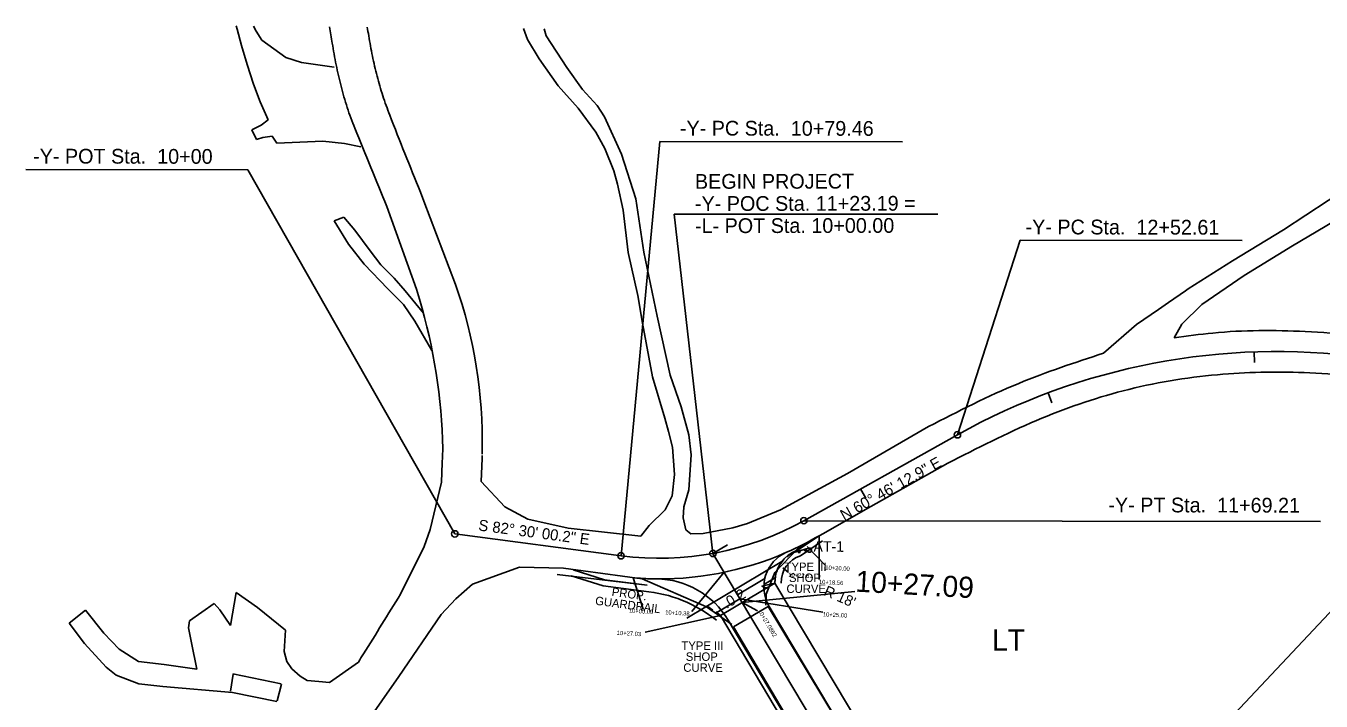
# Model space of a CAD drawing. Extents: x 757145 to 758829, y 592169 to 594973.
# Drawn here: x 757323 to 757937, y 594652 to 594973 of the extents above; entities that cross this region are included whole.
import ezdxf

# ---------------------------------------------------------------- set-up
doc = ezdxf.new("R2010")
doc.units = 0
for name, color, linetype in [('COGO Default Point Elevation', 7, 'Continuous'), ('Default', 7, 'Continuous'), ('Exist Horizontal Alignment', 7, 'Continuous'), ('Exist Horizontal Alignment Direction Label', 7, 'Continuous'), ('Exist Horizontal Alignment Station Label', 7, 'Continuous'), ('Exist Horizontal Alignment Tick Small', 7, 'Continuous'), ('Prop Dimension', 7, 'Continuous'), ('Prop EOT', 7, 'Continuous'), ('Prop Guardrail Anchor Unit CELL', 7, 'Continuous'), ('Prop Guardrail Shop Curved', 7, 'Continuous'), ('Prop Horizontal Alignment Direction Label', 7, 'Continuous'), ('Prop Horizontal Alignment Tick Small', 7, 'Continuous'), ('Prop Paved Shoulder', 7, 'Continuous'), ('Prop Rem of Exist Asph Pvmt', 7, 'Continuous'), ('Prop Roadway Bridge', 7, 'Continuous'), ('Prop Structure Anchor Unit CELL', 7, 'Continuous'), ('Prop Superelevation  Arrow CELL', 7, 'Continuous'), ('Scratch_Level_4', 7, 'Continuous')]:
    doc.layers.add(name, color=color, linetype=linetype)

msp = doc.modelspace()

# ---------------------------------------------------------------- linework, layer by layer
at = {"layer": 'COGO Default Point Elevation'}
for p, q in [((757689.05, 594723.55), (757692.46, 594724.51)), ((757689.05, 594723.55), (757689.73, 594723.74)), ((757689.27, 594722.78), (757689.05, 594723.55)), ((757689.05, 594723.55), (757689.94, 594722.96)), ((757689.73, 594723.74), (757689.27, 594722.78)), ((757689.94, 594722.96), (757689.27, 594722.78)), ((757689.73, 594723.74), (757689.94, 594722.96)), ((757691.98, 594724.37), (757692.65, 594724.56)), ((757692.2, 594723.6), (757691.98, 594724.37)), ((757691.98, 594724.37), (757692.87, 594723.79)), ((757692.65, 594724.56), (757692.2, 594723.6)), ((757692.87, 594723.79), (757692.2, 594723.6)), ((757692.53, 594724.53), (757692.4, 594724.49)), ((757692.53, 594724.53), (757692.4, 594724.49)), ((757692.46, 594724.51), (757694.12, 594724.97)), ((757692.65, 594724.56), (757692.75, 594724.22)), ((757692.65, 594724.56), (757692.75, 594724.22)), ((757692.65, 594724.56), (757692.87, 594723.79)), ((757693.78, 594723.23), (757692.82, 594723.97)), ((757681.31, 594718.64), (757636.34, 594691.82)), ((757660.32, 594702.85), (757673.24, 594710.55)), ((757672.8, 594707.74), (757678.13, 594710.92)), ((757650.45, 594694.41), (757661.44, 594700.97))]:
    msp.add_line(p, q, dxfattribs=at)
for points in [[(757698.92, 594710.07), (757698.96, 594730.84)], [(757701.95, 594716.8), (757693.23, 594725.75)], [(757615.51, 594695.98), (757610.85, 594710.9)], [(757638.68, 594694.86), (757653.95, 594713.53)], [(757684.37, 594713.38), (757681.75, 594715.63)], [(757700.78, 594694.56), (757661.44, 594700.97)], [(757669.81, 594695.16), (757662.51, 594699.18)], [(757616.45, 594685.11), (757652.18, 594693.08)]]:
    msp.add_lwpolyline(points, dxfattribs=at)
msp.add_lwpolyline([(757678.01, 594708.32), (757671.83, 594707), (757674.03, 594705.97)], close=True, dxfattribs=at)
msp.add_ellipse((757694.39, 594724.02), major_axis=(-0.268, 0.956), ratio=0.995379, start_param=2.210226, end_param=6.283185, dxfattribs=at)
at = {"layer": 'Default'}
for p, q in [((757423.26, 594970.9), (757422.7, 594972.52)), ((757425.18, 594963.15), (757423.26, 594970.9)), ((757430.89, 594972.44), (757432.26, 594970.02)), ((757432.26, 594970.02), (757434.96, 594965.68)), ((757558.81, 594971.28), (757560.74, 594966.05)), ((757568.63, 594971.19), (757569.64, 594967.81)), ((757427.93, 594954.21), (757425.18, 594963.15)), ((757434.96, 594965.68), (757446.28, 594957.48)), ((757560.74, 594966.05), (757566.33, 594956.95)), ((757569.64, 594967.81), (757579.41, 594952.72)), ((757446.28, 594957.48), (757453.72, 594955.16)), ((757566.33, 594956.95), (757575.26, 594944.1)), ((757430.93, 594944.82), (757427.93, 594954.21)), ((757453.72, 594955.16), (757469.17, 594952.98)), ((757579.41, 594952.72), (757586.89, 594942.33)), ((757434.12, 594936.47), (757430.93, 594944.82)), ((757575.26, 594944.1), (757584.82, 594933.45)), ((757586.89, 594942.33), (757593.71, 594934.86)), ((757437.85, 594928.03), (757434.12, 594936.47)), ((757584.82, 594933.45), (757593.16, 594922.16)), ((757597.32, 594929.47), (757593.71, 594934.86)), ((757430.17, 594923.29), (757434.51, 594925.52)), ((757434.51, 594925.52), (757437.85, 594928.03)), ((757597.32, 594929.47), (757605.37, 594911.77)), ((757432.29, 594918.66), (757430.17, 594923.29)), ((757435.38, 594919.64), (757432.31, 594918.66)), ((757439.81, 594920.25), (757435.38, 594919.64)), ((757441.96, 594917), (757439.81, 594920.25)), ((757593.16, 594922.16), (757597.48, 594914.35)), ((757432.31, 594918.66), (757432.29, 594918.66)), ((757463.75, 594917.95), (757441.96, 594917)), ((757474, 594916.83), (757463.75, 594917.95)), ((757481.86, 594915.17), (757474, 594916.83)), ((757597.48, 594914.35), (757601.7, 594903.82)), ((757605.37, 594911.77), (757612.13, 594890.5)), ((757601.7, 594903.82), (757603.45, 594897.45)), ((757603.45, 594897.45), (757606.15, 594885.14)), ((757918.98, 594875.82), (757952.2, 594897.78)), ((757511.72, 594889.44), (757510.06, 594893.76)), ((757526.63, 594849.91), (757511.72, 594889.44)), ((757612.13, 594890.5), (757615.84, 594865.29)), ((757923.25, 594868.26), (757966.66, 594893.94)), ((757494.16, 594886.93), (757508.12, 594847.7)), ((757606.15, 594885.14), (757608.52, 594865.11)), ((757469.15, 594880.12), (757473.67, 594881.91)), ((757476.01, 594869.03), (757469.15, 594880.12)), ((757473.67, 594881.91), (757479.01, 594875.74)), ((757479.01, 594875.74), (757486.25, 594865.85)), ((757894.9, 594861.12), (757918.98, 594875.82)), ((757483.38, 594859.6), (757476.01, 594869.03)), ((757486.25, 594865.85), (757491.31, 594859.28)), ((757608.52, 594865.11), (757613.02, 594844.75)), ((757615.84, 594865.29), (757622.27, 594834.96)), ((757900.31, 594854.25), (757923.25, 594868.26)), ((757494.57, 594847.94), (757483.38, 594859.6)), ((757491.31, 594859.28), (757497.67, 594852.98)), ((757873.88, 594847.82), (757894.9, 594861.12)), ((757497.67, 594852.98), (757502.79, 594846.94)), ((757880.33, 594840.47), (757900.31, 594854.25)), ((757501.95, 594840.38), (757494.57, 594847.94)), ((757502.79, 594846.94), (757511.52, 594836.4)), ((757508.12, 594847.7), (757509.56, 594842.92)), ((757864.58, 594841.45), (757872.59, 594846.95)), ((757872.59, 594846.95), (757873.88, 594847.82)), ((757507.44, 594832.58), (757501.95, 594840.38)), ((757613.02, 594844.75), (757615.2, 594831.59)), ((757859.72, 594838.05), (757864.58, 594841.45)), ((757870.8, 594831.08), (757880.33, 594840.47)), ((757628.42, 594806.97), (757622.27, 594834.96)), ((757849.4, 594830.99), (757859.72, 594838.05)), ((757515.51, 594818.65), (757507.44, 594832.58)), ((757615.2, 594831.59), (757619.97, 594806.13)), ((757833.68, 594817.38), (757849.4, 594830.99)), ((757867.17, 594824.62), (757870.8, 594831.08)), ((757619.97, 594806.13), (757625.78, 594786.52)), ((757633.59, 594791.87), (757628.42, 594806.97)), ((757633.59, 594791.87), (757637.19, 594778.68)), ((757625.78, 594786.52), (757627.64, 594780.23)), ((757629.54, 594772.83), (757627.64, 594780.23)), ((757637.19, 594778.68), (757638.26, 594769.12)), ((757750.76, 594782.54), (757712.4, 594760.37)), ((757520.59, 594772.11), (757520.36, 594765.05)), ((757630.39, 594759.79), (757629.54, 594772.83)), ((757519.95, 594756.28), (757520.33, 594765.47)), ((757539.35, 594767.49), (757538.84, 594756.62)), ((757539.25, 594769.5), (757539.22, 594771.23)), ((757539.29, 594768.81), (757539.35, 594767.49)), ((757638.26, 594769.12), (757637.2, 594752.56)), ((757629.3, 594749.68), (757630.39, 594759.79)), ((757712.4, 594760.37), (757680.65, 594743.18)), ((757723.49, 594744.76), (757759.9, 594765.22)), ((757538.84, 594756.62), (757550.07, 594744.6)), ((757626.02, 594743.1), (757629.3, 594749.68)), ((757637.2, 594752.56), (757634.83, 594744.49)), ((757550.07, 594744.6), (757560.92, 594738.65)), ((757618.42, 594735.63), (757626.02, 594743.1)), ((757634.83, 594744.49), (757634.5, 594739.33)), ((757680.65, 594743.18), (757665.08, 594736.68)), ((757560.92, 594738.65), (757580.09, 594734.41)), ((757614.51, 594730.61), (757618.42, 594735.63)), ((757634.5, 594739.33), (757635.82, 594733.69)), ((757658, 594734.6), (757665.08, 594736.68)), ((757580.09, 594734.41), (757614.51, 594730.61)), ((757635.82, 594733.69), (757638.23, 594731.77)), ((757638.23, 594731.77), (757643.98, 594731.82)), ((757643.98, 594731.82), (757658, 594734.6)), ((757534.78, 594707.93), (757526.78, 594700.88)), ((757400.58, 594690.5), (757412.35, 594698.79)), ((757412.35, 594698.79), (757414.95, 594695.65)), ((757420.03, 594688.24), (757422.77, 594703.93)), ((757422.77, 594703.93), (757432.85, 594696.85)), ((757526.78, 594700.88), (757519.93, 594693.54)), ((757343.61, 594689.37), (757351.37, 594695.52)), ((757351.37, 594695.52), (757359.96, 594684.61)), ((757414.95, 594695.65), (757420.03, 594688.24)), ((757432.85, 594696.85), (757446.1, 594686.14)), ((757658.35, 594687.7), (757674.88, 594697.27)), ((757674.88, 594697.27), (757706.73, 594644.4)), ((757350.87, 594679.82), (757343.61, 594689.37)), ((757400.06, 594687.14), (757400.58, 594690.5)), ((757401.5, 594680.14), (757400.06, 594687.14)), ((757446.1, 594686.14), (757445.53, 594676.02)), ((757700.05, 594617.37), (757658.35, 594687.7)), ((757361.09, 594668.6), (757350.87, 594679.82)), ((757359.96, 594684.61), (757367.33, 594677.09)), ((757404.15, 594667.6), (757401.5, 594680.14)), ((757367.33, 594677.09), (757376.5, 594671.26)), ((757445.53, 594676.02), (757446.75, 594671.15)), ((757365.9, 594664.69), (757361.09, 594668.6)), ((757376.5, 594671.26), (757388.53, 594669.82)), ((757388.53, 594669.82), (757404.15, 594667.6)), ((757446.75, 594671.15), (757449.17, 594667.76)), ((757449.17, 594667.76), (757453, 594664.26)), ((757466.98, 594661.19), (757480.66, 594670.98)), ((757376.61, 594660.69), (757365.9, 594664.69)), ((757421.36, 594665.18), (757420.04, 594657.09)), ((757444.04, 594660.67), (757421.1, 594665.45)), ((757453, 594664.26), (757456.44, 594662.25)), ((757456.44, 594662.25), (757461.89, 594661.73)), ((757461.89, 594661.73), (757466.98, 594661.19)), ((757387.91, 594659.34), (757376.61, 594660.69)), ((757421.04, 594656.49), (757387.91, 594659.34)), ((757442.04, 594652.32), (757421.04, 594656.49)), ((757442.19, 594652.58), (757444.17, 594660.54))]:
    msp.add_line(p, q, dxfattribs=at)
for points in [[(757500.54, 594703.08), (757511.83, 594725.74), (757514.69, 594733.79), (757519.95, 594756.28)], [(757519.93, 594693.54), (757499.75, 594664.06), (757475.67, 594629.54), (757450.9, 594594.8)]]:
    msp.add_lwpolyline(points, dxfattribs=at)
for centre, major_axis, ratio, start_param, end_param in [((757319.23, 594776.33), (15.83, 219.6), 0.999445, 4.761154, 5.12504), ((757264.11, 594768.46), (-41.51, 256.49), 0.986972, 4.56805, 4.844759)]:
    msp.add_ellipse(centre, major_axis=major_axis, ratio=ratio, start_param=start_param, end_param=end_param, dxfattribs=at)
for points in [[(757467.01, 594972.12), (757468.24, 594964.36), (757469.11, 594959.21), (757470.09, 594954.07), (757472.42, 594943.87), (757475.34, 594933.83), (757477.04, 594928.9), (757478.93, 594924.04), (757494.16, 594886.93)], [(757510.06, 594893.76), (757495.51, 594930.24), (757492.22, 594939.39), (757489.5, 594948.74), (757487.29, 594958.24), (757486.36, 594963.02), (757485.53, 594967.81), (757484.86, 594971.95)], [(758438.83, 594691.7), (758388.12, 594713.96), (758348.23, 594729.88), (758301, 594745.68), (758262.18, 594757.5), (758218.1, 594769.85), (758179.06, 594780.3), (758137.21, 594790.72), (758099.24, 594799.92), (758057.04, 594808.54), (758015.02, 594816.54), (757976.3, 594823.06), (757929.26, 594827.65), (757885.54, 594826.92), (757867.17, 594824.62)], [(757833.68, 594817.38), (757793.57, 594803.08), (757750.76, 594782.54)], [(757759.9, 594765.22), (757801.95, 594785.45), (757843.04, 594799.54), (757887.75, 594807.17), (757928.75, 594808.19), (757973.34, 594803.82), (758011.28, 594797.5), (758054.09, 594789.21), (758096.75, 594780.39), (758132.99, 594771.58), (758175.84, 594760.81), (758214.12, 594750.43), (758258.48, 594738.29), (758295.65, 594726.54), (758342.77, 594710.33), (758380.69, 594695.36), (758421.02, 594677.79), (758431.33, 594673.19)], [(757480.66, 594670.98), (757483.04, 594674.79), (757500.54, 594703.08)]]:
    msp.add_spline(points, degree=3, dxfattribs=at)
at = {"layer": 'Exist Horizontal Alignment'}
for p, q in [((757691.73, 594737.96), (757764.52, 594778.69)), ((757526.32, 594731.71), (757605.1, 594721.34))]:
    msp.add_line(p, q, dxfattribs=at)
for centre, radius, start, end in [((757915.89, 594508.17), 310, 82.43399, 119.22975), ((757623.37, 594860.14), 140, 262.50005, 299.22975)]:
    msp.add_arc(centre, radius, start, end, dxfattribs=at)
at = {"layer": 'Exist Horizontal Alignment Station Label'}
for p, q in [((757605.1, 594721.34), (757623.45, 594917.75)), ((757623.45, 594917.75), (757738.49, 594917.54)), ((757323.09, 594904.49), (757428.27, 594904.3)), ((757526.32, 594731.71), (757428.27, 594904.3)), ((757764.52, 594778.69), (757794.27, 594870.94)), ((757794.27, 594870.94), (757899.45, 594870.74)), ((757691.73, 594737.96), (757936.61, 594737.52))]:
    msp.add_line(p, q, dxfattribs=at)
for centre in [(757764.52, 594778.69), (757691.73, 594737.96), (757526.32, 594731.71), (757605.1, 594721.34)]:
    msp.add_circle(centre, 1.5, dxfattribs=at)
at = {"layer": 'Exist Horizontal Alignment Tick Small'}
for p, q in [((757905.14, 594817.98), (757905.31, 594812.98)), ((757807.48, 594798.59), (757809.23, 594793.9)), ((757718.61, 594753), (757721.05, 594748.64))]:
    msp.add_line(p, q, dxfattribs=at)
at = {"layer": 'Prop Dimension'}
for p, q in [((757687.01, 594722.88), (757694.12, 594724.97)), ((757680.75, 594717.73), (757682.26, 594719.7)), ((757683.62, 594720.85), (757685.56, 594722.2)), ((757574.81, 594712.47), (757617.46, 594707.38)), ((757678.03, 594708.32), (757678.25, 594711.56)), ((757645.69, 594697.59), (757648.62, 594695.63)), ((757650.06, 594694.7), (757652.17, 594693.07))]:
    msp.add_line(p, q, dxfattribs=at)
msp.add_lwpolyline([(757715.95, 594704.36), (757662.51, 594699.18)], dxfattribs=at)
at = {"layer": 'Prop EOT'}
msp.add_line((757648.63, 594722.44), (757655.5, 594726.54), dxfattribs=at)
at = {"layer": 'Prop Guardrail Anchor Unit CELL'}
for p, q in [((757675.24, 594697.36), (757741.82, 594585.76)), ((757655.82, 594690.87), (757724.64, 594575.51))]:
    msp.add_line(p, q, dxfattribs=at)
for centre, radius, start, end in [((757623.37, 594860.14), 149.77, 293.69101, 300.31092), ((757623.37, 594860.14), 149.77, 267.81103, 293.69101), ((757690.77, 594706.49), 18.02, 113.63532, 210.46289), ((757623.37, 594860.14), 149.77, 265.20481, 267.81103), ((757621.47, 594670.38), 40, 30.81837, 89.42564)]:
    msp.add_arc(centre, radius, start, end, dxfattribs=at)
at = {"layer": 'Prop Guardrail Shop Curved'}
for p, q in [((757687.01, 594722.88), (757685.56, 594722.2)), ((757679, 594714.37), (757678.64, 594713.19))]:
    msp.add_line(p, q, dxfattribs=at)
at = {"layer": 'Prop Horizontal Alignment Direction Label'}
for p, q in [((757723.49, 594744.76), (757689.39, 594725.28)), ((757645.66, 594697.19), (757615.09, 594710.35)), ((757657.67, 594688.76), (757645.66, 594697.19))]:
    msp.add_line(p, q, dxfattribs=at)
for points in [[(757689.39, 594725.28), (757677.91, 594713.34), (757673.81, 594703.14), (757673.78, 594697.89)], [(757615.09, 594710.35), (757577.79, 594715.4), (757556.93, 594715.9), (757534.78, 594707.93)]]:
    msp.add_lwpolyline(points, dxfattribs=at)
at = {"layer": 'Prop Horizontal Alignment Tick Small'}
msp.add_line((757648.63, 594722.44), (757733.23, 594580.63), dxfattribs=at)
at = {"layer": 'Prop Paved Shoulder'}
for p, q in [((757688.74, 594723.98), (757698.96, 594730.84)), ((757582.42, 594714.68), (757597.27, 594710)), ((757597.27, 594710), (757617.46, 594707.39)), ((757652.18, 594693.08), (757650.07, 594694.71))]:
    msp.add_line(p, q, dxfattribs=at)
msp.add_arc((757693.95, 594708.91), 15.95, 109.06732, 182.11639, dxfattribs=at)
at = {"layer": 'Prop Rem of Exist Asph Pvmt'}
msp.add_line((757613.12, 594710.87), (757613.07, 594710.66), dxfattribs=at)
at = {"layer": 'Prop Roadway Bridge'}
for p, q in [((757648.63, 594722.44), (757630.24, 594883.27)), ((757630.24, 594883.27), (757755.14, 594883.23)), ((757826.37, 594572.61), (757948.13, 594702.11))]:
    msp.add_line(p, q, dxfattribs=at)
msp.add_circle((757648.63, 594722.44), 1.5, dxfattribs=at)
at = {"layer": 'Prop Structure Anchor Unit CELL'}
for p, q in [((757652.18, 594693.08), (757678.01, 594708.32)), ((757678.01, 594708.32), (757754.32, 594580.41)), ((757652.18, 594693.08), (757731.58, 594559.96))]:
    msp.add_line(p, q, dxfattribs=at)
at = {"layer": 'Prop Superelevation  Arrow CELL'}
msp.add_line((757652.18, 594693.08), (757678.01, 594708.32), dxfattribs=at)
at = {"layer": 'Scratch_Level_4'}
for p, q in [((757690.07, 594721.27), (757700.63, 594728.35)), ((757581.52, 594711.82), (757596.62, 594707.06)), ((757596.62, 594707.06), (757615.96, 594704.52))]:
    msp.add_line(p, q, dxfattribs=at)
for centre, radius, start, end in [((757693.95, 594708.91), 12.95, 107.43015, 182.11639), ((757610.44, 594641.09), 63.67, 51.23971, 85.0249)]:
    msp.add_arc(centre, radius, start, end, dxfattribs=at)

# ---------------------------------------------------------------- texts
at = {"layer": 'COGO Default Point Elevation'}
for s, height, rotation, p in [('AT-1', 5, 359.89587, (757696.28, 594723.23)), ('TYPE III', 4, 359.89587, (757682.58, 594714.13)), ('10+20.00', 2, 356.78993, (757701.84, 594714.8)), ('10+22.81', 2, 356.78993, (757684.26, 594711.38)), ('SHOP', 4, 359.89587, (757684.67, 594708.92)), ('PROP.', 4, 352.50005, (757600.5, 594702.36)), ('CURVE', 4, 359.89587, (757683.48, 594703.73)), ('10+18.56', 2, 356.78993, (757698.8, 594708.07)), ('GUARDRAIL', 4, 352.50005, (757592.65, 594698.15)), ('10+00.00', 2, 356.78993, (757608.74, 594694.35)), ('10+10.38', 2, 356.78993, (757625.97, 594693.57)), ('10+27.0862', 2, 300.81837, (757669.82, 594695.16)), ('10+25.00', 2, 356.78993, (757700.67, 594692.66)), ('10+27.03', 2, 356.78993, (757603.02, 594683.86)), ('TYPE III', 4, 359.89587, (757633.7, 594676.74)), ('SHOP', 4, 359.89587, (757635.78, 594671.54)), ('CURVE', 4, 359.89587, (757634.59, 594666.34))]:
    msp.add_text(s, height=height, rotation=rotation, dxfattribs=at).set_placement(p)
at = {"layer": 'Exist Horizontal Alignment Direction Label'}
for s, rotation, p in [('N 60%%d 46\' 12.9" E', 29.22975, (757710.79, 594737.88)), ('S 82%%d 30\' 00.2" E', 352.50005, (757537.27, 594733.37))]:
    msp.add_text(s, height=5.25, rotation=rotation, dxfattribs=at).set_placement(p)
at = {"layer": 'Exist Horizontal Alignment Station Label'}
for s, p in [('-Y- PC Sta.  10+79.46', (757632.98, 594920.56)), ('-Y- POT Sta.  10+00', (757326.51, 594907.29)), ('-Y- PC Sta.  12+52.61', (757796.77, 594873.73)), ('-Y- PT Sta.  11+69.21', (757836.03, 594741.96))]:
    msp.add_text(s, height=7, rotation=359.89587, dxfattribs=at).set_placement(p)
at = {"layer": 'Prop Dimension'}
for s, height, rotation, p in [('10+27.09', 10, 356.78993, (757715.95, 594704.36)), ("R 18'", 5, 336.2752, (757700.79, 594702.82)), ('LT', 10, 359.9825, (757780.93, 594676.43))]:
    msp.add_text(s, height=height, rotation=rotation, dxfattribs=at).set_placement(p)
at = {"layer": 'Prop Roadway Bridge'}
for s, p in [('BEGIN PROJECT', (757640.11, 594895.29)), ('-Y- POC Sta. 11+23.19 =', (757640.12, 594884.79)), ('-L- POT Sta. 10+00.00', (757640.14, 594874.29))]:
    msp.add_text(s, height=7, rotation=0.08364, dxfattribs=at).set_placement(p)
at = {"layer": 'Prop Superelevation  Arrow CELL'}
msp.add_text('.0 2', height=5, rotation=30.51858, dxfattribs=at).set_placement((757655.11, 594696.11))

doc.saveas('drawing.dxf')
